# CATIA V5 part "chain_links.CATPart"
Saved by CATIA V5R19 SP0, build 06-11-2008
Part number: chain_links
Bounding box of the stored display mesh (mm): x -80 to 20, y -20 to 20, z -25 to 15
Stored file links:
  D:\VKW\Work\Process_And_Tools\Courseware_Development\Tangix_Certification_Project\Preparation_Kit\CATIA V5 Associate_Preparation kit\R19_Data\Chain Link Assembly\chain_links.CATPart
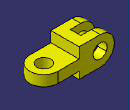
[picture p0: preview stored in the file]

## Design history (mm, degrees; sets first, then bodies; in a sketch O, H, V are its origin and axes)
Body1 (main body)
  Sketch1 on xy-plane, origin (0, 0, 0), H (1, 0, 0), V (0, 1, 0)
    arc A1 centre (0, 0) radius 20 from (0, -20) to (0, 20) ccw
    line L1 (0, 20) -> (-30, 20)
    line L2 (-30, 20) -> (-30, -20)
    line L3 (0, -20) -> (-30, -20)
    point P4 (0, -20)
    radius A1 = 20
    length L1 = 30
    tangency: L1 A1, L3 A1
    vertical: L2 V
    coincidence: P4 V
    horizontal: L1 H, L3 H
  Pad1: profile Sketch1, direction (0, 0, -1), length 15
  Sketch2 on zx-plane, origin (0, 0, 0), H (-1, 0, 0), V (0, 0, 1)
    line L1 (30, 15) -> (60, 15)
    line L2 (60, -25) -> (30, -25)
    line L3 (30, -25) -> (30, 15)
    arc A1 centre (60, -5) radius 20 from (60, -25) to (60, 15) ccw
    point P5 (60, -5)
    reference projected line E1 (0, 0) -> (30, 0) from edge [face of Pad1 from Sketch1.L1 | start face of Pad1]
    length L1 = 30
    distance V L3 = 30
    radius A1 = 20
    distance P5 E1 = 5
    horizontal: L1 H, L2 H
    vertical: L3 V
    tangency: A1 L2, A1 L1
  Pad2: profile Sketch2, direction (0, 1, 0), length 20, mirrored extent
  Sketch3 on xy-plane, origin (0, 0, 0), H (1, 0, 0), V (0, 1, 0)
    line L1 (-95, 7.5) -> (-45, 7.5)
    line L2 (-45, 7.5) -> (-45, -7.5)
    line L3 (-45, -7.5) -> (-95, -7.5)
    line L4 (-95, -7.5) -> (-95, 7.5)
    distance V L2 = 45
    length L1 = 50
    length L4 = 15
    distance L1 H = 7.5
    horizontal: L1 H, L3 H
    vertical: L2 V, L4 V
  Pocket1: profile Sketch3, direction (0, 0, -1), through (limit type 3), opposite side through (limit type 3)
  Sketch4 on face of Pad2, origin (-57.7311, 20, -4.1115), H (1, 0, 0), V (0, 0, -1)
    point P1 (-2.2689, 0.8885)
    reference projected arc E1 centre (-2.2689, 0.8885) radius 20 from (-2.2689, 20.8885) to (-2.2689, -19.1115) ccw from edge [face of Pad2 from Sketch2.A1 | end face of Pad2]
    concentricity: P1 E1
  Hole1: placed by Sketch4, at (-60, 20, -5) direction (0, -1, 0), diameter 20, depth 40
  Sketch5 on start face of Pad1, origin (-11.3203, 0.8793, 0), H (1, 0, 0), V (0, 1, 0)
    point P1 (11.3203, -0.8793)
    reference projected arc E1 centre (11.3203, -0.8793) radius 20 from (11.3203, -20.8793) to (11.3203, 19.1207) ccw from edge [face of Pad1 from Sketch1.A1 | start face of Pad1]
    concentricity: P1 E1
  Hole2: placed by Sketch5, at (0, 0, 0) direction (0, 0, -1), diameter 20, through (limit type 3)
